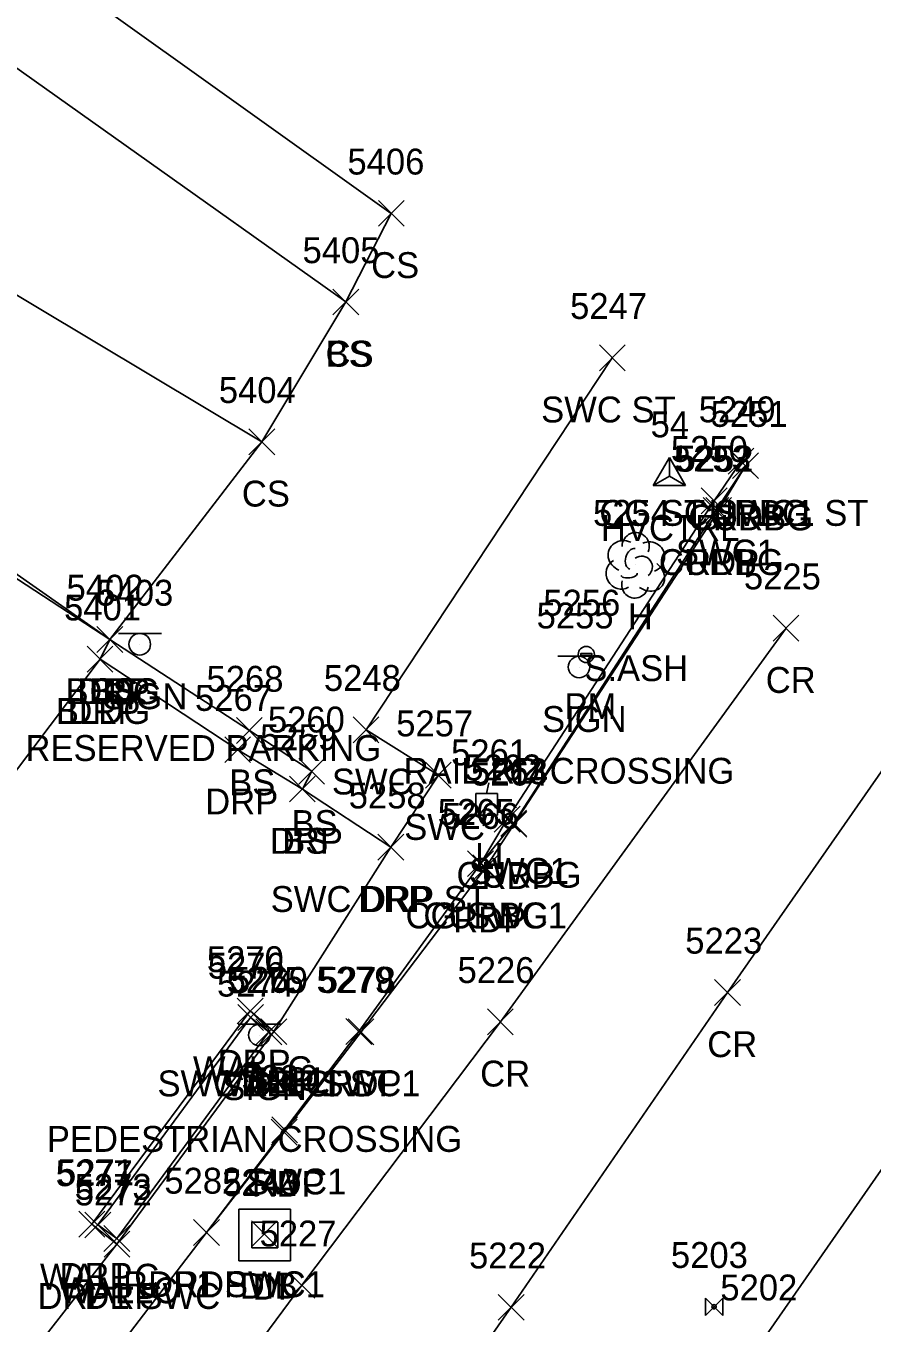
# Model space of a CAD drawing. Extents: x 1618146 to 1620418, y 640749 to 641927.
# Drawn here: x 1620304 to 1620369.4, y 641036.5 to 641136.7 of the extents above; entities that cross this region are included whole.
import ezdxf

# ---------------------------------------------------------------- set-up
doc = ezdxf.new("R2010")
doc.units = 0
for name, color, linetype in [('C_A', 7, 'Continuous'), ('C_I', 7, 'Continuous'), ('CPSM', 7, 'Continuous'), ('D_A', 7, 'Continuous'), ('D_I', 7, 'Continuous'), ('D_TIC', 7, 'Continuous'), ('DS', 7, 'Continuous'), ('L_A', 7, 'Continuous'), ('L_C', 7, 'Continuous'), ('L_I', 7, 'Continuous'), ('L_TIC', 7, 'Continuous'), ('LBC', 7, 'Continuous'), ('LELB', 7, 'Continuous'), ('LTD', 7, 'Continuous'), ('LW', 7, 'Continuous'), ('P_A', 7, 'Continuous'), ('P_I', 7, 'Continuous'), ('P_TIC', 7, 'Continuous'), ('PET', 7, 'Continuous'), ('PRC', 7, 'Continuous'), ('R_A', 7, 'Continuous'), ('R_I', 7, 'Continuous'), ('R_TIC', 7, 'Continuous'), ('RC', 7, 'Continuous'), ('RDP', 7, 'Continuous'), ('RSW', 7, 'Continuous'), ('S_A', 7, 'Continuous'), ('S_C', 7, 'Continuous'), ('S_I', 7, 'Continuous'), ('SPM', 7, 'Continuous'), ('SSGN', 7, 'Continuous'), ('U_A', 7, 'Continuous'), ('U_I', 7, 'Continuous'), ('ULP', 7, 'Continuous'), ('UWV', 7, 'Continuous')]:
    doc.layers.add(name, color=color, linetype=linetype)

msp = doc.modelspace()

# ---------------------------------------------------------------- linework, layer by layer
at = {"layer": 'CPSM'}
for p, q in [((1620352.5, 641101.2), (1620353.75, 641103.37)), ((1620355, 641101.2), (1620353.75, 641103.37)), ((1620353.75, 641101.93), (1620353.75, 641103.37)), ((1620352.5, 641101.2), (1620353.75, 641101.93)), ((1620353.75, 641101.93), (1620353.75, 641101.93)), ((1620353.75, 641101.93), (1620355, 641101.2)), ((1620352.5, 641101.2), (1620355, 641101.2))]:
    msp.add_line(p, q, dxfattribs=at)
at = {"layer": 'D_TIC'}
for points in [[(1620321.44, 641042.37), (1620323.44, 641044.37)], [(1620323.44, 641042.37), (1620321.44, 641044.37)]]:
    msp.add_lwpolyline(points, dxfattribs=at)
at = {"layer": 'DS'}
for p, q in [((1620320.47, 641045.29), (1620324.47, 641045.29)), ((1620320.47, 641041.29), (1620320.47, 641045.29)), ((1620324.47, 641045.29), (1620324.47, 641041.29)), ((1620321.47, 641042.29), (1620321.47, 641044.29)), ((1620321.47, 641044.29), (1620323.47, 641044.29)), ((1620323.47, 641044.29), (1620323.47, 641042.29)), ((1620322.48, 641043.29), (1620322.48, 641043.29)), ((1620322.48, 641043.29), (1620322.48, 641043.29)), ((1620323.47, 641042.29), (1620321.47, 641042.29)), ((1620324.47, 641041.29), (1620320.47, 641041.29))]:
    msp.add_line(p, q, dxfattribs=at)
at = {"layer": 'L_TIC'}
for points in [[(1620331.25, 641121.24), (1620333.25, 641123.24)], [(1620333.25, 641121.24), (1620331.25, 641123.24)], [(1620327.73, 641114.39), (1620329.73, 641116.39)], [(1620329.73, 641114.39), (1620327.73, 641116.39)], [(1620327.73, 641114.39), (1620329.73, 641116.39)], [(1620329.73, 641114.39), (1620327.73, 641116.39)], [(1620321.25, 641103.58), (1620323.25, 641105.58)], [(1620323.25, 641103.58), (1620321.25, 641105.58)], [(1620321.25, 641103.58), (1620323.25, 641105.58)], [(1620323.25, 641103.58), (1620321.25, 641105.58)], [(1620309.49, 641088.31), (1620311.49, 641090.31)], [(1620311.49, 641088.31), (1620309.49, 641090.31)], [(1620309.49, 641088.31), (1620311.49, 641090.31)], [(1620311.49, 641088.31), (1620309.49, 641090.31)], [(1620309.49, 641088.31), (1620311.49, 641090.31)], [(1620311.49, 641088.31), (1620309.49, 641090.31)], [(1620308.74, 641086.78), (1620310.74, 641088.78)], [(1620310.74, 641086.78), (1620308.74, 641088.78)], [(1620320.28, 641081.27), (1620322.28, 641083.27)], [(1620322.28, 641081.27), (1620320.28, 641083.27)], [(1620325.1, 641078.12), (1620327.1, 641080.12)], [(1620327.1, 641078.12), (1620325.1, 641080.12)], [(1620324.38, 641076.75), (1620326.38, 641078.75)], [(1620326.38, 641076.75), (1620324.38, 641078.75)], [(1620320.38, 641059.1), (1620322.38, 641061.1)], [(1620322.38, 641059.1), (1620320.38, 641061.1)], [(1620321.78, 641057.99), (1620323.78, 641059.99)], [(1620323.78, 641057.99), (1620321.78, 641059.99)], [(1620308.57, 641043.06), (1620310.57, 641045.06)], [(1620310.57, 641043.06), (1620308.57, 641045.06)], [(1620308.57, 641043.06), (1620310.57, 641045.06)], [(1620310.57, 641043.06), (1620308.57, 641045.06)], [(1620310.04, 641042.01), (1620312.04, 641044.01)], [(1620312.04, 641042.01), (1620310.04, 641044.01)], [(1620310.04, 641042.01), (1620312.04, 641044.01)], [(1620312.04, 641042.01), (1620310.04, 641044.01)]]:
    msp.add_lwpolyline(points, dxfattribs=at)
at = {"layer": 'LBC'}
msp.add_lwpolyline([(1620279.79, 641047.68), (1620291.77, 641063.86), (1620292.8, 641063.13), (1620293.75, 641064.21), (1620298.39, 641070.47), (1620299.24, 641071.59), (1620298.22, 641072.52), (1620309.74, 641087.78), (1620310.49, 641089.31), (1620280.23, 641109.06), (1620260.19, 641122.08), (1620237.42, 641090.89)], dxfattribs=at)
at = {"layer": 'LELB'}
for points in [[(1620322.25, 641104.58), (1620328.73, 641115.39), (1620332.25, 641122.24), (1620297.17, 641147.26), (1620261.97, 641167), (1620254.96, 641172.98), (1620251.38, 641166.83), (1620241.33, 641155.99)], [(1620328.73, 641115.39), (1620294.75, 641139.53), (1620257.99, 641160.06), (1620251.38, 641166.83)], [(1620310.49, 641089.31), (1620322.25, 641104.58), (1620287.41, 641125.43), (1620251.67, 641148.83), (1620241.33, 641155.99)], [(1620325.38, 641077.75), (1620326.1, 641079.12), (1620321.28, 641082.27), (1620310.49, 641089.31)]]:
    msp.add_lwpolyline(points, dxfattribs=at)
at = {"layer": 'LTD'}
msp.add_line((1620351.1, 641095.09), (1620351.1, 641095.09), dxfattribs=at)
msp.add_line((1620351.1, 641095.09), (1620351.1, 641095.09), dxfattribs=at)
msp.add_arc((1620351.14, 641096.52), 1.05, 335.5272, 180.9563, dxfattribs=at)
for centre, major_axis, ratio, start_param, end_param in [((1620350.3, 641095.75), (1.21, -0.51), 0.895232, 1.570796, 4.712389), ((1620350.89, 641095.54), (-0.208, -0.792), 0.645439, 3.141593, 6.283185), ((1620352.14, 641095.67), (-1.14, -0.48), 0.949671, 1.570796, 4.712389), ((1620350.01, 641094.38), (0.58, -1.04), 0.959034, 3.141593, 6.283185), ((1620351.6, 641094.92), (-0.5, 0.667), 0.989748, 3.141593, 6.283185), ((1620350.64, 641094.34), (-0.625, -0.083), 0.423636, 0, 3.141593), ((1620352.1, 641094.25), (-1.09, 0.79), 0.841452, 1.570796, 4.712389), ((1620351.1, 641093.59), (0.26, 1.06), 0.942809, 1.570796, 4.712389)]:
    msp.add_ellipse(centre, major_axis=major_axis, ratio=ratio, start_param=start_param, end_param=end_param, dxfattribs=at)
at = {"layer": 'LW'}
for points in [[(1620311.04, 641043.01), (1620322.78, 641058.99), (1620321.38, 641060.1), (1620309.57, 641044.06)], [(1620311.04, 641043.01), (1620309.57, 641044.06)]]:
    msp.add_lwpolyline(points, dxfattribs=at)
at = {"layer": 'P_TIC'}
for points in [[(1620358.62, 641101.74), (1620360.62, 641103.74)], [(1620360.62, 641101.74), (1620358.62, 641103.74)], [(1620356.55, 641098.28), (1620358.55, 641100.28)], [(1620358.55, 641098.28), (1620356.55, 641100.28)], [(1620361.76, 641089.18), (1620363.76, 641091.18)], [(1620363.76, 641089.18), (1620361.76, 641091.18)], [(1620340.73, 641074.02), (1620342.73, 641076.02)], [(1620342.73, 641074.02), (1620340.73, 641076.02)], [(1620338.54, 641070.67), (1620340.54, 641072.67)], [(1620340.54, 641070.67), (1620338.54, 641072.67)], [(1620357.23, 641061.03), (1620359.23, 641063.03)], [(1620359.23, 641061.03), (1620357.23, 641063.03)], [(1620339.68, 641058.76), (1620341.68, 641060.76)], [(1620341.68, 641058.76), (1620339.68, 641060.76)], [(1620328.91, 641057.99), (1620330.91, 641059.99)], [(1620330.91, 641057.99), (1620328.91, 641059.99)], [(1620322.97, 641050.24), (1620324.97, 641052.24)], [(1620324.97, 641050.24), (1620322.97, 641052.24)], [(1620316.97, 641042.48), (1620318.97, 641044.48)], [(1620318.97, 641042.48), (1620316.97, 641044.48)], [(1620324.33, 641038.4), (1620326.33, 641040.4)], [(1620326.33, 641038.4), (1620324.33, 641040.4)], [(1620340.52, 641036.7), (1620342.52, 641038.7)], [(1620342.52, 641036.7), (1620340.52, 641038.7)]]:
    msp.add_lwpolyline(points, dxfattribs=at)
at = {"layer": 'PET'}
msp.add_lwpolyline([(1620359.62, 641102.74), (1620357.55, 641099.28), (1620341.73, 641075.02), (1620339.54, 641071.67), (1620329.91, 641058.99), (1620323.97, 641051.24), (1620317.97, 641043.48), (1620299.64, 641019.57), (1620282.8, 640996.95), (1620281.46, 640995.25), (1620278.2, 640990.78), (1620276.89, 640989.31), (1620275.83, 640987.69), (1620269.89, 640979.34), (1620267.26, 640975.91), (1620246.8, 640948.47), (1620237.1, 640935.68), (1620207.92, 640898.41)], dxfattribs=at)
at = {"layer": 'PRC'}
for points in [[(1620362.76, 641090.18), (1620340.68, 641059.76), (1620325.33, 641039.4), (1620305.34, 641012.42), (1620285.98, 640987.1), (1620282.92, 640982.14), (1620262.65, 640955.36), (1620239.62, 640925.27), (1620211.72, 640891.88)], [(1620224.8, 640884.19), (1620252.42, 640919.67), (1620271.91, 640945.14), (1620290.44, 640967.96), (1620293.94, 640972.26), (1620320.64, 641007.74), (1620341.52, 641037.7), (1620358.23, 641062.03), (1620372.9, 641083.07)], [(1620386.4, 641071.71), (1620361.02, 641035.23), (1620336.24, 641002.91), (1620316.22, 640977.17), (1620300.32, 640960.31), (1620296.61, 640956.78), (1620272.86, 640927.85), (1620252.18, 640901.58), (1620233.9, 640877.59)]]:
    msp.add_lwpolyline(points, dxfattribs=at)
at = {"layer": 'R_TIC'}
for points in [[(1620348.33, 641110.08), (1620350.33, 641112.08)], [(1620350.33, 641110.08), (1620348.33, 641112.08)], [(1620358.28, 641102.09), (1620360.28, 641104.09)], [(1620360.28, 641102.09), (1620358.28, 641104.09)], [(1620358.28, 641102.09), (1620360.28, 641104.09)], [(1620360.28, 641102.09), (1620358.28, 641104.09)], [(1620358.62, 641101.74), (1620360.62, 641103.74)], [(1620360.62, 641101.74), (1620358.62, 641103.74)], [(1620356.21, 641099.03), (1620358.21, 641101.03)], [(1620358.21, 641099.03), (1620356.21, 641101.03)], [(1620356.35, 641098.29), (1620358.35, 641100.29)], [(1620358.35, 641098.29), (1620356.35, 641100.29)], [(1620309.49, 641088.31), (1620311.49, 641090.31)], [(1620311.49, 641088.31), (1620309.49, 641090.31)], [(1620308.74, 641086.78), (1620310.74, 641088.78)], [(1620310.74, 641086.78), (1620308.74, 641088.78)], [(1620329.3, 641081.33), (1620331.3, 641083.33)], [(1620331.3, 641081.33), (1620329.3, 641083.33)], [(1620319.38, 641079.79), (1620321.38, 641081.79)], [(1620321.38, 641079.79), (1620319.38, 641081.79)], [(1620334.89, 641077.82), (1620336.89, 641079.82)], [(1620336.89, 641077.82), (1620334.89, 641079.82)], [(1620324.38, 641076.75), (1620326.38, 641078.75)], [(1620326.38, 641076.75), (1620324.38, 641078.75)], [(1620340.21, 641074.42), (1620342.21, 641076.42)], [(1620342.21, 641074.42), (1620340.21, 641076.42)], [(1620340.71, 641074.12), (1620342.71, 641076.12)], [(1620342.71, 641074.12), (1620340.71, 641076.12)], [(1620331.22, 641072.25), (1620333.22, 641074.25)], [(1620333.22, 641072.25), (1620331.22, 641074.25)], [(1620331.22, 641072.25), (1620333.22, 641074.25)], [(1620333.22, 641072.25), (1620331.22, 641074.25)], [(1620338.15, 641070.98), (1620340.15, 641072.98)], [(1620340.15, 641070.98), (1620338.15, 641072.98)], [(1620338.15, 641070.98), (1620340.15, 641072.98)], [(1620340.15, 641070.98), (1620338.15, 641072.98)], [(1620320.34, 641059.6), (1620322.34, 641061.6)], [(1620322.34, 641059.6), (1620320.34, 641061.6)], [(1620322.17, 641058), (1620324.17, 641060)], [(1620324.17, 641058), (1620322.17, 641060)], [(1620322.17, 641058), (1620324.17, 641060)], [(1620324.17, 641058), (1620322.17, 641060)], [(1620328.74, 641058.01), (1620330.74, 641060.01)], [(1620330.74, 641058.01), (1620328.74, 641060.01)], [(1620323.01, 641050.42), (1620325.01, 641052.42)], [(1620325.01, 641050.42), (1620323.01, 641052.42)], [(1620308.11, 641043.13), (1620310.11, 641045.13)], [(1620310.11, 641043.13), (1620308.11, 641045.13)], [(1620316.97, 641042.48), (1620318.97, 641044.48)], [(1620318.97, 641042.48), (1620316.97, 641044.48)], [(1620310.05, 641041.57), (1620312.05, 641043.57)], [(1620312.05, 641041.57), (1620310.05, 641043.57)], [(1620310.05, 641041.57), (1620312.05, 641043.57)], [(1620312.05, 641041.57), (1620310.05, 641043.57)]]:
    msp.add_lwpolyline(points, dxfattribs=at)
at = {"layer": 'RC'}
msp.add_lwpolyline([(1620359.28, 641103.09), (1620359.62, 641102.74), (1620357.35, 641099.29), (1620341.71, 641075.12), (1620339.15, 641071.98)], dxfattribs=at)
at = {"layer": 'RDP'}
for points in [[(1620310.49, 641089.31), (1620281.04, 641109.93), (1620259.98, 641123.17)], [(1620332.22, 641073.25), (1620325.38, 641077.75), (1620320.38, 641080.79), (1620309.74, 641087.78)], [(1620323.17, 641059), (1620321.34, 641060.6), (1620309.11, 641044.13), (1620311.05, 641042.57)]]:
    msp.add_lwpolyline(points, dxfattribs=at)
at = {"layer": 'RSW'}
for points in [[(1620349.33, 641111.08), (1620330.3, 641082.33), (1620335.89, 641078.82), (1620332.22, 641073.25), (1620323.17, 641059), (1620311.05, 641042.57), (1620292.45, 641018.75), (1620282.83, 641005.9)], [(1620359.28, 641103.09), (1620357.21, 641100.03), (1620341.21, 641075.42), (1620339.15, 641071.98), (1620329.74, 641059.01), (1620324.01, 641051.42), (1620317.97, 641043.48)]]:
    msp.add_lwpolyline(points, dxfattribs=at)
at = {"layer": 'SPM'}
msp.add_lwpolyline([(1620346.9, 641088.07), (1620347.74, 641088.07), (1620347.74, 641088.23), (1620346.9, 641088.23)], close=True, dxfattribs=at)
msp.add_circle((1620347.32, 641088.15), 0.625, dxfattribs=at)
at = {"layer": 'SSGN'}
for p, q in [((1620311.16, 641089.77), (1620314.5, 641089.77)), ((1620312.81, 641088.94), (1620312.81, 641088.94)), ((1620345.11, 641088.02), (1620348.45, 641088.02)), ((1620346.76, 641087.18), (1620346.76, 641087.18)), ((1620320.41, 641059.57), (1620323.74, 641059.57)), ((1620322.05, 641058.74), (1620322.05, 641058.74))]:
    msp.add_line(p, q, dxfattribs=at)
for centre in [(1620312.81, 641088.94), (1620346.76, 641087.18), (1620322.05, 641058.74)]:
    msp.add_circle(centre, 0.833, dxfattribs=at)
at = {"layer": 'ULP'}
for p, q in [((1620338.78, 641075.74), (1620338.78, 641077.41)), ((1620338.78, 641077.41), (1620340.45, 641077.41)), ((1620339.78, 641078.24), (1620339.61, 641077.41)), ((1620340.45, 641077.41), (1620340.45, 641075.74)), ((1620339.61, 641076.58), (1620339.61, 641076.58)), ((1620340.45, 641075.74), (1620338.78, 641075.74)), ((1620339.36, 641074.91), (1620339.61, 641075.74))]:
    msp.add_line(p, q, dxfattribs=at)
at = {"layer": 'UWV'}
for p, q in [((1620356.53, 641038.41), (1620357.87, 641037.07)), ((1620357.87, 641038.41), (1620356.53, 641037.07))]:
    msp.add_line(p, q, dxfattribs=at)
for points in [[(1620356.53, 641038.41), (1620356.53, 641037.07)], [(1620357.87, 641037.07), (1620357.87, 641038.41)]]:
    msp.add_lwpolyline(points, dxfattribs=at)
msp.add_circle((1620357.2, 641037.74), 0.167, dxfattribs=at)

# ---------------------------------------------------------------- texts
at = {"layer": 'C_A'}
msp.add_text('HVCTRL', height=2, dxfattribs=at).set_placement((1620348.45, 641096.93))
at = {"layer": 'C_I'}
msp.add_text('54', height=2, dxfattribs=at).set_placement((1620352.29, 641104.93))
at = {"layer": 'D_A'}
for s, p in [('DIB', (1620320.54, 641038.37)), ('DI', (1620321.53, 641038.29))]:
    msp.add_text(s, height=2, dxfattribs=at).set_placement(p)
at = {"layer": 'D_I'}
for s, p in [('5243', (1620319.18, 641046.37)), ('5244', (1620319.22, 641046.29))]:
    msp.add_text(s, height=2, dxfattribs=at).set_placement(p)
at = {"layer": 'L_A'}
for s, p in [('CS', (1620330.69, 641117.24)), ('CS', (1620327.17, 641110.39)), ('BS', (1620327.17, 641110.39)), ('CS', (1620320.7, 641099.58)), ('CS', (1620320.7, 641099.58)), ('H', (1620350.53, 641090.09)), ('BLDG', (1620307.08, 641084.31)), ('CS', (1620308.93, 641084.31)), ('BS', (1620308.93, 641084.31)), ('BLDG', (1620306.33, 641082.78)), ('BS', (1620319.72, 641077.27)), ('BS', (1620324.54, 641074.12)), ('BS', (1620323.82, 641072.75)), ('WALLC', (1620316.92, 641055.1)), ('WALLC', (1620318.31, 641053.99)), ('WALLC', (1620305.1, 641039.06)), ('WALLC', (1620305.1, 641039.06)), ('WALLC', (1620306.57, 641038.01)), ('WALLC', (1620306.57, 641038.01))]:
    msp.add_text(s, height=2, dxfattribs=at).set_placement(p)
at = {"layer": 'L_C'}
msp.add_text('S.ASH', height=2, dxfattribs=at).set_placement((1620347.17, 641086.09))
at = {"layer": 'L_I'}
for s, p in [('5406', (1620328.86, 641125.24)), ('5405', (1620325.39, 641118.39)), ('5405', (1620325.39, 641118.39)), ('5404', (1620318.92, 641107.58)), ('5404', (1620318.92, 641107.58)), ('5254', (1620347.84, 641098.09)), ('5402', (1620307.15, 641092.31)), ('5402', (1620307.15, 641092.31)), ('5402', (1620307.15, 641092.31)), ('5401', (1620306.96, 641090.78)), ('5268', (1620317.97, 641085.27)), ('5260', (1620322.71, 641082.12)), ('5259', (1620322.11, 641080.75)), ('5276', (1620318.07, 641063.1)), ('5275', (1620319.52, 641061.99)), ('5277', (1620306.31, 641047.06)), ('5277', (1620306.31, 641047.06)), ('5273', (1620307.78, 641046.01)), ('5273', (1620307.78, 641046.01))]:
    msp.add_text(s, height=2, dxfattribs=at).set_placement(p)
at = {"layer": 'P_A'}
for s, p in [('RDP', (1620357.11, 641097.74)), ('RDP', (1620355.04, 641094.28)), ('CR', (1620361.19, 641085.18)), ('RDP', (1620339.22, 641070.02)), ('RDP', (1620337.03, 641066.67)), ('CR', (1620356.67, 641057.03)), ('CR', (1620339.12, 641054.76)), ('RDP', (1620327.4, 641053.99)), ('RDP', (1620321.46, 641046.24)), ('RDP', (1620315.46, 641038.48))]:
    msp.add_text(s, height=2, dxfattribs=at).set_placement(p)
at = {"layer": 'P_I'}
for s, p in [('5251', (1620356.93, 641105.74)), ('5252', (1620354.29, 641102.28)), ('5225', (1620359.5, 641093.18)), ('5264', (1620338.42, 641078.02)), ('5266', (1620336.18, 641074.67)), ('5223', (1620354.97, 641065.03)), ('5226', (1620337.37, 641062.76)), ('5278', (1620326.65, 641061.99)), ('5281', (1620321.28, 641054.24)), ('5282', (1620314.71, 641046.48)), ('5227', (1620322.07, 641042.4)), ('5222', (1620338.26, 641040.7)), ('5202', (1620357.68, 641038.23))]:
    msp.add_text(s, height=2, dxfattribs=at).set_placement(p)
at = {"layer": 'R_A'}
for s, p in [('SWC ST', (1620343.83, 641106.08)), ('CG ST SWC1 ST', (1620348.33, 641098.09)), ('CURBG', (1620354.86, 641098.09)), ('CURBG', (1620355.2, 641097.74)), ('SWC1', (1620354.25, 641095.03)), ('CURBG', (1620352.93, 641094.29)), ('DRP', (1620307.98, 641084.31)), ('DRP', (1620307.22, 641082.78)), ('SWC', (1620327.66, 641077.33)), ('DRP', (1620317.87, 641075.79)), ('SWC', (1620333.25, 641073.82)), ('DRP', (1620322.87, 641072.75)), ('SWC1', (1620338.25, 641070.42)), ('CURBG', (1620337.29, 641070.12)), ('SWC DRP ST', (1620322.93, 641068.25)), ('DRP', (1620329.7, 641068.25)), ('CG SWC1', (1620333.35, 641066.98)), ('CURBG', (1620334.73, 641066.98)), ('DRP', (1620318.83, 641055.6)), ('SWC DRP1 ST', (1620314.18, 641054)), ('DRP', (1620320.66, 641054)), ('SWC1', (1620326.78, 641054.01)), ('SWC1', (1620321.05, 641046.42)), ('DRP', (1620306.6, 641039.13)), ('RDP1 SWC1', (1620311.52, 641038.48)), ('DRP1 SWC', (1620304.91, 641037.57)), ('DRP', (1620308.53, 641037.57))]:
    msp.add_text(s, height=2, dxfattribs=at).set_placement(p)
at = {"layer": 'R_I'}
for s, p in [('5247', (1620346.07, 641114.08)), ('5249', (1620356.01, 641106.09)), ('5249', (1620356.01, 641106.09)), ('5251', (1620356.93, 641105.74)), ('5250', (1620353.86, 641103.03)), ('5253', (1620354.09, 641102.29)), ('5402', (1620307.15, 641092.31)), ('5401', (1620306.96, 641090.78)), ('5248', (1620327.04, 641085.33)), ('5267', (1620317.08, 641083.79)), ('5257', (1620332.63, 641081.82)), ('5259', (1620322.11, 641080.75)), ('5262', (1620337.9, 641078.42)), ('5263', (1620338.4, 641078.12)), ('5258', (1620328.96, 641076.25)), ('5258', (1620328.96, 641076.25)), ('5265', (1620335.84, 641074.98)), ('5265', (1620335.84, 641074.98)), ('5270', (1620317.99, 641063.6)), ('5269', (1620319.86, 641062)), ('5269', (1620319.86, 641062)), ('5279', (1620326.47, 641062.01)), ('5280', (1620320.67, 641054.42)), ('5271', (1620306.42, 641047.13)), ('5282', (1620314.71, 641046.48)), ('5272', (1620307.79, 641045.57)), ('5272', (1620307.79, 641045.57))]:
    msp.add_text(s, height=2, dxfattribs=at).set_placement(p)
at = {"layer": 'S_A'}
for s, p in [('SIGN', (1620309.95, 641083.92)), ('PM', (1620345.63, 641083.15)), ('SIGN', (1620343.9, 641082.16)), ('SIGN', (1620319.19, 641053.71))]:
    msp.add_text(s, height=2, dxfattribs=at).set_placement(p)
at = {"layer": 'S_C'}
for s, p in [('PRIVATE RESERVED PARKING', (1620291.79, 641079.92)), ('RAIL RD CROSSING', (1620333.2, 641078.16)), ('PEDESTRIAN CROSSING', (1620305.63, 641049.71))]:
    msp.add_text(s, height=2, dxfattribs=at).set_placement(p)
at = {"layer": 'S_I'}
for s, p in [('5403', (1620309.45, 641091.92)), ('5256', (1620344, 641091.15)), ('5255', (1620343.48, 641090.16)), ('5274', (1620318.78, 641061.71))]:
    msp.add_text(s, height=2, dxfattribs=at).set_placement(p)
at = {"layer": 'U_A'}
msp.add_text('LI', height=2, dxfattribs=at).set_placement((1620338.72, 641071.58))
at = {"layer": 'U_I'}
for s, p in [('5261', (1620336.87, 641079.58)), ('5203', (1620353.86, 641040.74))]:
    msp.add_text(s, height=2, dxfattribs=at).set_placement(p)

doc.saveas('drawing.dxf')
